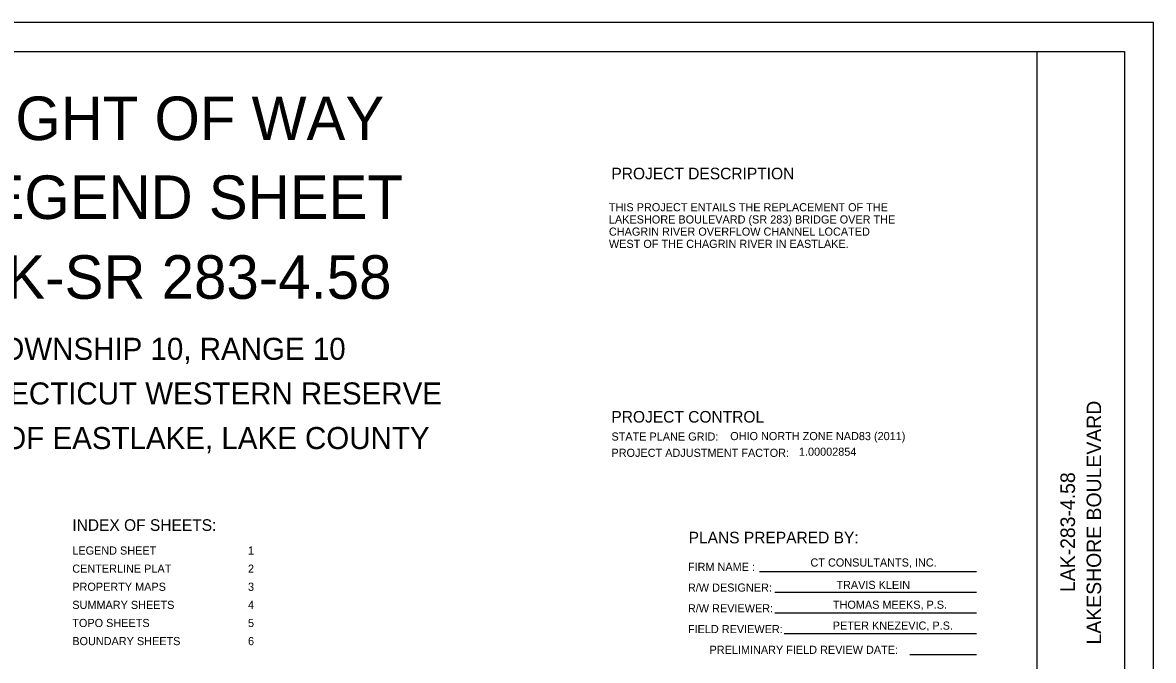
# Model space of a CAD drawing. Extents: x 0 to 34, y 0 to 22.
# Drawn here: x 14.53 to 34, y 11.01 to 22 of the extents above; entities that cross this region are included whole.
import ezdxf

# ---------------------------------------------------------------- set-up
doc = ezdxf.new("R2010")
doc.units = 0
for name, color, linetype in [('Default', 7, 'Continuous'), ('SH_Border', 7, 'Continuous'), ('SH_Cut_Line', 7, 'Continuous'), ('SH_Data', 7, 'Continuous'), ('SH_Text', 7, 'Continuous'), ('SN_P_Text', 7, 'Continuous')]:
    doc.layers.add(name, color=color, linetype=linetype)

msp = doc.modelspace()

# ---------------------------------------------------------------- linework, layer by layer
at = {"layer": 'Default'}
msp.add_line((1.5, 21.5), (32, 21.5), dxfattribs=at)
at = {"layer": 'SH_Border'}
msp.add_line((32, 0.5), (32, 21.5), dxfattribs=at)
msp.add_lwpolyline([(1.5, 21.5), (33.5, 21.5), (33.5, 0.5), (1.5, 0.5)], close=True, dxfattribs=at)
at = {"layer": 'SH_Cut_Line'}
msp.add_lwpolyline([(0, 0), (34, 0), (34, 22), (0, 22)], close=True, dxfattribs=at)
at = {"layer": 'SH_Text'}
for p, q in [((27.216, 12.544), (30.953, 12.544)), ((27.48, 12.187), (30.953, 12.187)), ((27.48, 11.83), (30.953, 11.83)), ((27.644, 11.473), (30.953, 11.473)), ((29.808, 11.115), (30.953, 11.115))]:
    msp.add_line(p, q, dxfattribs=at)

# ---------------------------------------------------------------- texts
at = {"layer": 'SH_Data'}
for s, height, p in [('RIGHT OF WAY', 0.75, (13.399, 19.976)), ('LEGEND SHEET', 0.75, (13.33, 18.617)), ('LAK-SR 283-4.58', 0.75, (13.018, 17.242)), ('TOWNSHIP 10, RANGE 10', 0.38, (13.849, 16.19)), ('CONNECTICUT WESTERN RESERVE', 0.38, (12.798, 15.421)), ('CITY OF EASTLAKE, LAKE COUNTY', 0.38, (12.894, 14.653)), ('INDEX OF SHEETS:', 0.2, (15.381, 13.244)), ('LEGEND SHEET', 0.14, (15.381, 12.835)), ('1', 0.14, (18.407, 12.835)), ('CENTERLINE PLAT', 0.14, (15.381, 12.523)), ('2', 0.14, (18.407, 12.523)), ('PROPERTY MAPS', 0.14, (15.381, 12.211)), ('3', 0.14, (18.407, 12.211)), ('SUMMARY SHEETS', 0.14, (15.381, 11.899)), ('4', 0.14, (18.407, 11.899)), ('TOPO SHEETS', 0.14, (15.381, 11.587)), ('5', 0.14, (18.407, 11.587)), ('BOUNDARY SHEETS', 0.14, (15.381, 11.275)), ('6', 0.14, (18.407, 11.275))]:
    msp.add_text(s, height=height, dxfattribs=at).set_placement(p)
for s, p in [('LAKESHORE BOULEVARD', (33.1, 11.287)), ('LAK-283-4.58', (32.65, 12.19))]:
    msp.add_text(s, height=0.25, rotation=90, dxfattribs=at).set_placement(p)
at = {"layer": 'SH_Text'}
for s, height, p in [('THIS PROJECT ENTAILS THE REPLACEMENT OF THE', 0.14, (24.623, 18.749)), ('LAKESHORE BOULEVARD (SR 283) BRIDGE OVER THE ', 0.14, (24.623, 18.539)), ('CHAGRIN RIVER OVERFLOW CHANNEL LOCATED ', 0.14, (24.623, 18.329)), ('WEST OF THE CHAGRIN RIVER IN EASTLAKE.', 0.14, (24.623, 18.119)), ('PROJECT CONTROL', 0.2, (24.666, 15.109)), ('STATE PLANE GRID:', 0.14, (24.667, 14.799)), (' OHIO NORTH ZONE NAD83 (2011)', 0.14, (26.66, 14.807)), ('PROJECT ADJUSTMENT FACTOR:', 0.14, (24.667, 14.519)), ('1.00002854', 0.14, (27.896, 14.538)), ('PLANS PREPARED BY:', 0.2, (25.996, 13.029)), ('FIRM NAME :', 0.14, (25.984, 12.554)), ('R/W DESIGNER:', 0.14, (25.984, 12.197)), ('R/W REVIEWER:', 0.14, (25.984, 11.84)), ('FIELD REVIEWER:', 0.14, (25.984, 11.482)), ('PRELIMINARY FIELD REVIEW DATE:', 0.14, (26.356, 11.125))]:
    msp.add_text(s, height=height, dxfattribs=at).set_placement(p)
at = {"layer": 'SN_P_Text'}
for s, height, p in [('PROJECT DESCRIPTION', 0.2, (24.666, 19.3)), ('CT CONSULTANTS, INC.', 0.14, (28.094, 12.629)), ('TRAVIS KLEIN', 0.14, (28.54, 12.243)), ('THOMAS MEEKS, P.S.', 0.14, (28.481, 11.902)), ('PETER KNEZEVIC, P.S.', 0.14, (28.478, 11.542))]:
    msp.add_text(s, height=height, dxfattribs=at).set_placement(p)

doc.saveas('drawing.dxf')
